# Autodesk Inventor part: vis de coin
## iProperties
Shininess: 64.0
Length Units: 11269
Angle Units: 11279
Time Units: 11290
Mass Units: 11283
Length Display Precision: 3
Angle Display Precision: 2
Compacted: True
Part Number: vis de coin
Document SubType Name: Modeling
Created: 2004-12
Material: Par défaut
Designer: LEGERET Philippe
Density: 0.0
Volumn: 0.0
Area: 0.0
PropertySet Name: Model Information
Control State: 0
Master: False
Checked Out: False
Author: LEGERET Philippe
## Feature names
1. Révolution1 [Revolution]
2. Chanfrein1 [Chamfer]
3. Chanfrein2 [Chamfer]
4. Chanfrein3 [Chamfer]
5. Extrusion1
6. Symétrie1 [Mirror]
